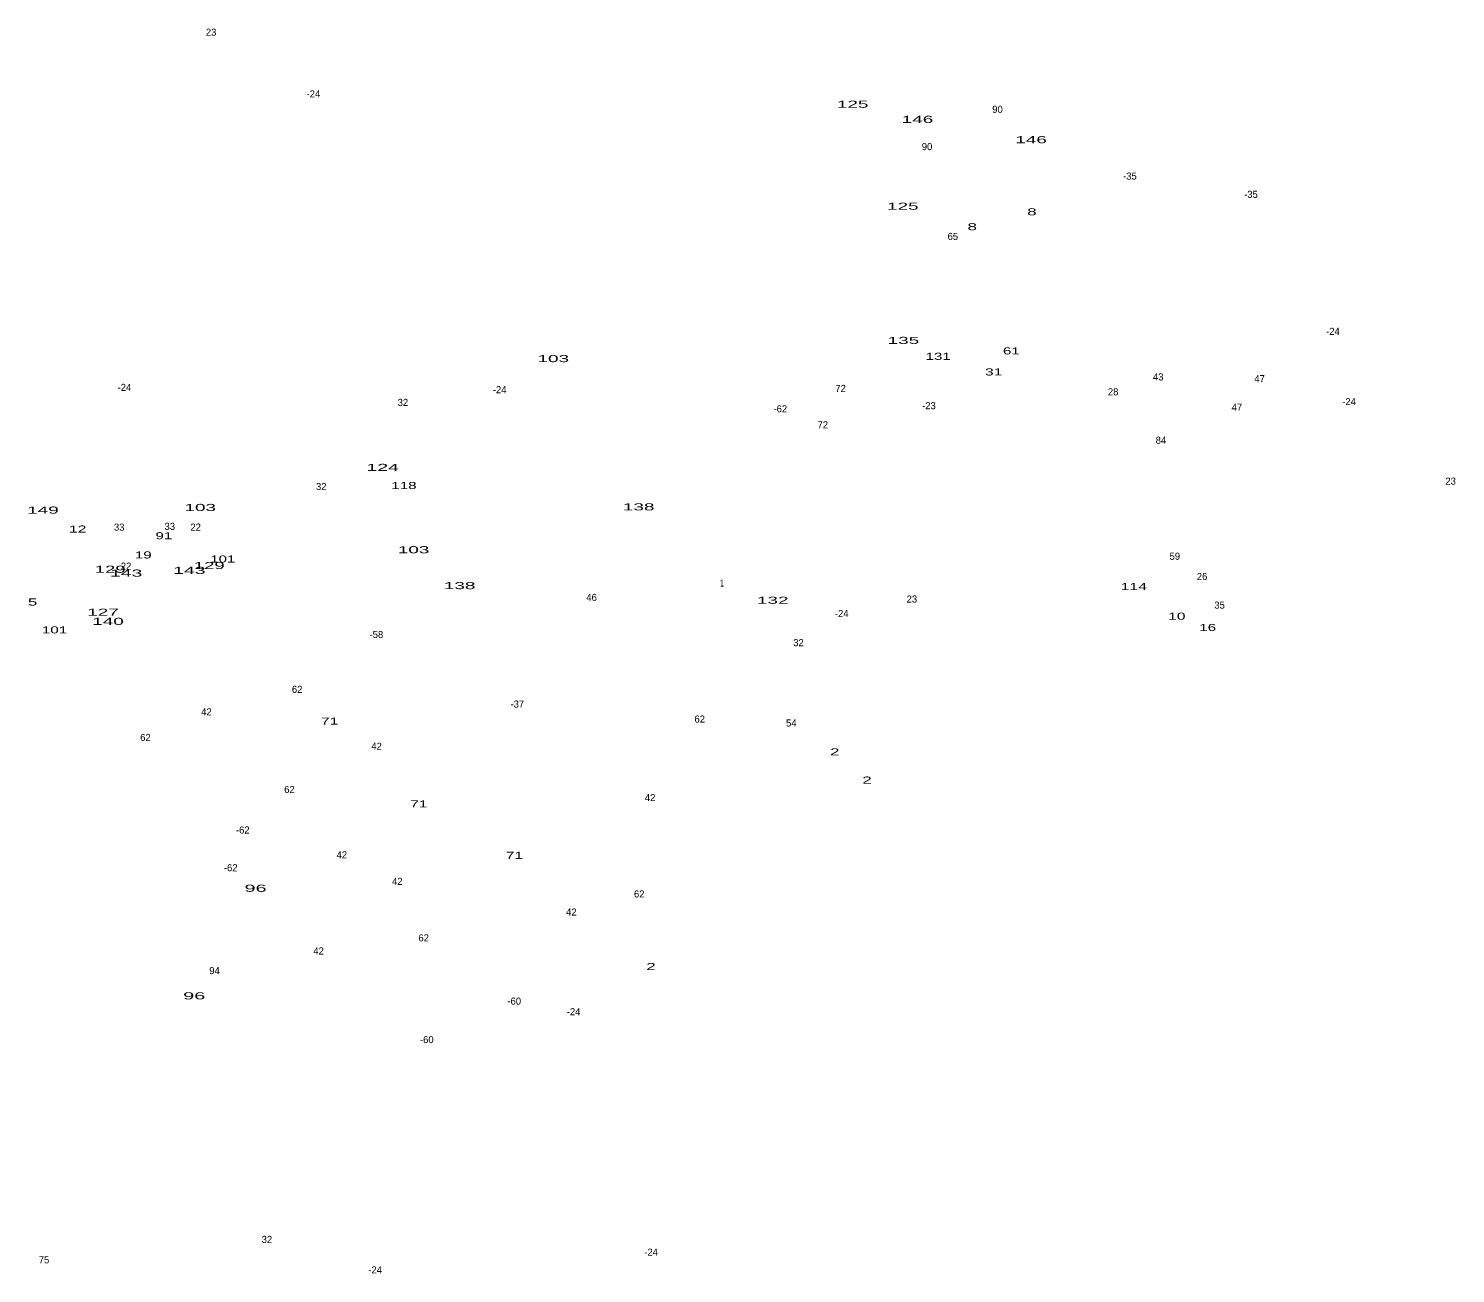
# Model space of a CAD drawing. Extents: x -672336 to -669011, y -998401 to -996613.
# Drawn here: x -670657 to -669851, y -997377 to -996673 of the extents above; entities that cross this region are included whole.
import ezdxf
from ezdxf.enums import TextEntityAlignment as Align

# ---------------------------------------------------------------- set-up
doc = ezdxf.new("R2010")
doc.units = 0
doc.header["$LTSCALE"] = 1.6
doc.layers.add('24', color=7, linetype='Continuous')

msp = doc.modelspace()

# ---------------------------------------------------------------- texts
at = {"layer": '24'}
for s, p in [('23', (-670553.817, -996676.93)), ('-24', (-670496.019, -996711.8)), ('90', (-670109.397, -996720.53)), ('90', (-670149.217, -996741.62)), ('-35', (-670034.565, -996758.28)), ('-35', (-669966.165, -996768.59)), ('65', (-670134.643, -996792.38)), ('-24', (-669919.839, -996846.06)), ('43', (-670018.601, -996871.82)), ('47', (-669961.257, -996872.79)), ('-24', (-670602.829, -996877.72)), ('-24', (-670390.749, -996879.01)), ('72', (-670198.063, -996878.3)), ('28', (-670044.047, -996880.23)), ('32', (-670445.457, -996886.2)), ('-62', (-670232.14, -996889.86)), ('-23', (-670148.155, -996888.05)), ('47', (-669974.137, -996888.96)), ('47', (-669974.137, -996888.96)), ('-24', (-669910.699, -996885.76)), ('72', (-670208.143, -996898.92)), ('84', (-670017.041, -996907.61)), ('23', (-669853.327, -996930.71)), ('32', (-670491.597, -996933.77)), ('33', (-670605.777, -996956.73)), ('33', (-670577.197, -996956.27)), ('22', (-670562.557, -996956.71)), ('22', (-670601.907, -996978.74)), ('59', (-670009.193, -996973.17)), ('26', (-669993.793, -996984.61)), ('46', (-670338.807, -996996.44)), ('23', (-670157.787, -996997.35)), ('35', (-669983.907, -997000.79)), ('-24', (-670197.449, -997005.55)), ('-58', (-670460.425, -997017.42)), ('32', (-670221.877, -997022.01)), ('62', (-670505.213, -997048.39)), ('-37', (-670380.801, -997056.75)), ('42', (-670556.451, -997061.12)), ('62', (-670277.693, -997065.2)), ('54', (-670225.931, -997067.43)), ('62', (-670590.943, -997075.6)), ('42', (-670460.301, -997080.56)), ('62', (-670509.573, -997105.03)), ('42', (-670305.721, -997109.62)), ('-62', (-670535.94, -997127.93)), ('-62', (-670542.74, -997149.26)), ('42', (-670479.981, -997141.96)), ('42', (-670448.591, -997156.96)), ('62', (-670311.893, -997164.08)), ('42', (-670350.221, -997174.3)), ('62', (-670433.683, -997188.92)), ('42', (-670493.091, -997196.32)), ('94', (-670551.897, -997207.42)), ('-60', (-670382.514, -997224.63)), ('-24', (-670348.979, -997230.65)), ('-60', (-670431.944, -997246.4)), ('32', (-670522.307, -997359.36)), ('-24', (-670305.149, -997366.57)), ('75', (-670648.273, -997370.92)), ('-24', (-670461.149, -997376.61))]:
    msp.add_text(s, height=4, dxfattribs=at).set_placement(p, align=Align.CENTER)
for s, width, p in [('125', 2, (-670191.247, -996717.66)), ('146', 2, (-670154.618, -996726.21)), ('146', 2, (-670090.438, -996737.7)), ('125', 2, (-670162.897, -996775.31)), ('8', 1.8, (-670089.971, -996778.47)), ('8', 1.8, (-670123.701, -996786.9)), ('135', 2, (-670162.557, -996851.15)), ('61', 1.6, (-670101.583, -996857.1)), ('103', 2, (-670360.454, -996861.46)), ('131', 1.6, (-670142.954, -996860.16)), ('31', 1.65, (-670111.557, -996868.99)), ('124', 2.05, (-670456.863, -996922.94)), ('118', 1.6, (-670444.864, -996933.19)), ('149', 2, (-670648.898, -996947.08)), ('103', 2, (-670559.974, -996945.59)), ('138', 2, (-670312.187, -996945.26)), ('12', 1.65, (-670629.267, -996957.81)), ('91', 1.6, (-670580.523, -996961.58)), ('103', 2, (-670439.394, -996969.49)), ('19', 1.6, (-670592.173, -996972.44)), ('129', 1.95, (-670554.893, -996978.42)), ('101', 1.6, (-670547.25, -996974.74)), ('129', 1.95, (-670610.883, -996980.53)), ('143', 2.05, (-670601.833, -996982.68)), ('143', 2.05, (-670566.113, -996981.16)), ('138', 2, (-670413.377, -996989.78)), ('1', 0.65, (-670265.107, -996988.33)), ('114', 1.65, (-670032.339, -996990.28)), ('5', 1.8, (-670654.721, -996999.05)), ('132', 2, (-670236.457, -996998.04)), ('127', 2, (-670614.913, -997004.78)), ('140', 2, (-670612.099, -997009.99)), ('10', 1.65, (-670008.054, -997007.04)), ('101', 1.6, (-670642.35, -997014.81)), ('16', 1.6, (-669990.613, -997013.43)), ('71', 1.65, (-670486.843, -997066.34)), ('2', 1.8, (-670201.391, -997083.76)), ('2', 1.8, (-670183.121, -997099.7)), ('71', 1.65, (-670436.483, -997113.19)), ('71', 1.65, (-670382.383, -997142.25)), ('96', 2.1, (-670528.711, -997160.85)), ('2', 1.8, (-670305.261, -997205.09)), ('96', 2.1, (-670563.381, -997221.67))]:
    msp.add_text(s, height=4, dxfattribs=dict(at, width=width)).set_placement(p, align=Align.CENTER)

doc.saveas('drawing.dxf')
